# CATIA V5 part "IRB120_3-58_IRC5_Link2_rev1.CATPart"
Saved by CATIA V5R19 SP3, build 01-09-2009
Part number: Link2
Revision: ANY
Definition: UNKNOWN
Nomenclature: Link2
Source: Unknown
Bounding box of the stored display mesh (mm): x -72.43 to 72.43, y -109.953 to 109.453, z 217.572 to 608.43
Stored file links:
  Z:\Projects\ABB_Robotics\ABB LIB\V5\V5PARTS\ABB\120\IRB120_3-58_IRC5_Link2_rev1.CATPart
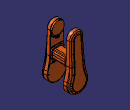
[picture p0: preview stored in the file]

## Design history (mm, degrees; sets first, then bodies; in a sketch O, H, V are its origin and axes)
Body1 "NONE" (main body)
  Solid1: solid without history
Body2 "NONE"
  Solid2: solid without history
Body3 "NONE"
  Solid3: solid without history
Body4 "NONE"
  Solid4: solid without history
Body5 "NONE"
  Solid5: solid without history
Body6 "NONE"
  Solid6: solid without history
Body7 "NONE"
  Solid7: solid without history
Body8 "NONE"
  Solid8: solid without history
Body9 "NONE"
  Solid9: solid without history
Body10 "NONE"
  Solid10: solid without history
